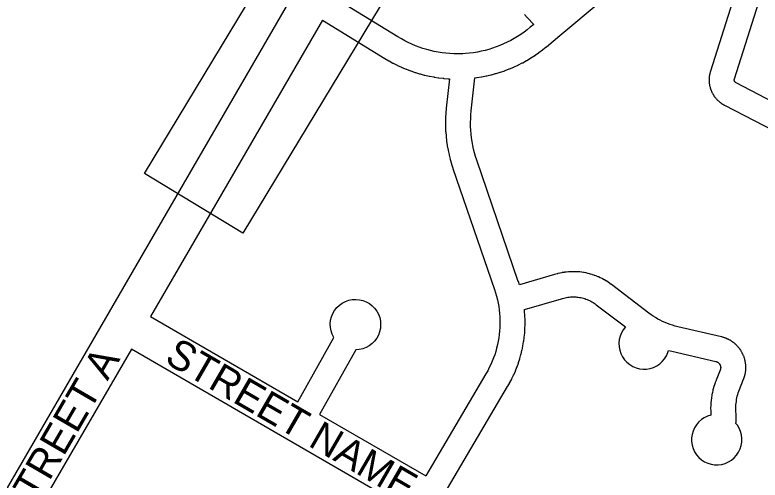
# Model space of a CAD drawing. Extents: x 599744 to 600217, y 4827560 to 4828065.
# Drawn here: x 600007.45 to 600025.18, y 4827978.51 to 4827989.56 of the extents above; entities that cross this region are included whole.
import ezdxf

# ---------------------------------------------------------------- set-up
doc = ezdxf.new("R2010")
doc.units = 0
doc.layers.add('G-ANNO-KEYP', color=7, linetype='Continuous')

msp = doc.modelspace()

# ---------------------------------------------------------------- linework, layer by layer
at = {"layer": 'G-ANNO-KEYP'}
msp.add_lwpolyline([(600010.535, 4827985.796), (600028.374, 4828015.258), (600030.714, 4828013.841), (600012.874, 4827984.379)], close=True, dxfattribs=at)
msp.add_lwpolyline([(600010.535, 4827985.796), (600028.374, 4828015.258), (600030.714, 4828013.841), (600012.874, 4827984.379)], close=True, dxfattribs=at)
for points in [[(600024.631, 4827990.207), (600023.999, 4827988.222), (600023.999, 4827988.219), (600023.997, 4827988.217), (600023.993, 4827988.204), (600023.993, 4827988.199), (600023.991, 4827988.194), (600023.987, 4827988.181), (600023.987, 4827988.175), (600023.985, 4827988.17), (600023.982, 4827988.157), (600023.981, 4827988.151), (600023.98, 4827988.146), (600023.977, 4827988.133), (600023.977, 4827988.126), (600023.975, 4827988.123), (600023.973, 4827988.109)], [(600024.569, 4827987.995), (600024.569, 4827987.998), (600024.568, 4827988), (600024.567, 4827988.003), (600024.567, 4827988.006), (600024.567, 4827988.009), (600024.566, 4827988.011), (600024.566, 4827988.014), (600024.566, 4827988.016), (600024.566, 4827988.019), (600024.566, 4827988.022), (600024.566, 4827988.025), (600024.567, 4827988.027), (600024.567, 4827988.03), (600024.568, 4827988.033), (600024.568, 4827988.035), (600024.569, 4827988.038), (600024.57, 4827988.043), (600025.2, 4827990.023)], [(600005.355, 4827974.888), (600005.664, 4827975.381), (600005.716, 4827975.467), (600005.764, 4827975.555), (600006.681, 4827977.304), (600006.685, 4827977.31), (600006.685, 4827977.312), (600006.748, 4827977.426), (600006.753, 4827977.433), (600006.753, 4827977.435), (600014.004, 4827989.912)], [(600019.578, 4827989.574), (600019.642, 4827989.504), (600019.795, 4827989.334), (600019.715, 4827989.268), (600019.64, 4827989.207), (600019.565, 4827989.151), (600019.489, 4827989.097), (600019.41, 4827989.046), (600019.33, 4827988.998), (600019.248, 4827988.953), (600019.165, 4827988.911), (600019.08, 4827988.871), (600018.993, 4827988.834), (600018.906, 4827988.801), (600018.818, 4827988.77), (600018.728, 4827988.743), (600018.638, 4827988.719), (600018.547, 4827988.697), (600018.455, 4827988.679), (600018.362, 4827988.665), (600018.27, 4827988.653), (600018.176, 4827988.645), (600018.108, 4827988.641), (600018.108, 4827988.641), (600018.083, 4827988.639), (600017.989, 4827988.638), (600017.896, 4827988.639), (600017.802, 4827988.643), (600017.709, 4827988.651), (600017.616, 4827988.662), (600017.524, 4827988.677), (600017.431, 4827988.694), (600017.34, 4827988.715), (600017.25, 4827988.739), (600017.16, 4827988.765), (600017.071, 4827988.796), (600016.984, 4827988.828), (600016.898, 4827988.865), (600016.813, 4827988.904), (600016.728, 4827988.946), (600016.647, 4827988.99), (600016.564, 4827989.039), (600015.071, 4827989.958)], [(600020.096, 4827988.806), (600020.097, 4827988.806), (600020.417, 4827989.073), (600021.425, 4827989.916)], [(600014.77, 4827989.44), (600010.677, 4827982.397)], [(600014.77, 4827989.44), (600016.252, 4827988.528), (600016.253, 4827988.528), (600016.257, 4827988.525), (600016.346, 4827988.472), (600016.348, 4827988.472), (600016.355, 4827988.467), (600016.446, 4827988.418), (600016.449, 4827988.417), (600016.456, 4827988.413), (600016.549, 4827988.366), (600016.551, 4827988.366), (600016.558, 4827988.362), (600016.652, 4827988.318), (600016.656, 4827988.318), (600016.662, 4827988.314), (600016.758, 4827988.274), (600016.762, 4827988.273), (600016.767, 4827988.27), (600016.865, 4827988.233), (600016.869, 4827988.233), (600016.875, 4827988.23), (600016.973, 4827988.197), (600016.978, 4827988.196), (600016.983, 4827988.193), (600017.082, 4827988.164), (600017.088, 4827988.163), (600017.092, 4827988.161), (600017.193, 4827988.134), (600017.199, 4827988.134), (600017.203, 4827988.132), (600017.305, 4827988.109), (600017.311, 4827988.109), (600017.315, 4827988.107), (600017.417, 4827988.087), (600017.424, 4827988.087), (600017.427, 4827988.086), (600017.53, 4827988.07), (600017.537, 4827988.07), (600017.54, 4827988.068), (600017.643, 4827988.056), (600017.651, 4827988.056), (600017.654, 4827988.055), (600017.757, 4827988.046), (600017.791, 4827988.047), (600017.715, 4827987.343), (600017.715, 4827987.339), (600017.714, 4827987.338), (600017.705, 4827987.237), (600017.705, 4827987.229)], [(600018.31, 4827987.281), (600018.396, 4827988.065), (600018.442, 4827988.071), (600018.442, 4827988.071), (600018.452, 4827988.073), (600018.555, 4827988.089), (600018.555, 4827988.089), (600018.565, 4827988.091), (600018.667, 4827988.111), (600018.668, 4827988.111), (600018.677, 4827988.113), (600018.778, 4827988.136), (600018.78, 4827988.137), (600018.788, 4827988.139), (600018.889, 4827988.166), (600018.891, 4827988.167), (600018.899, 4827988.169), (600018.998, 4827988.199), (600019, 4827988.201), (600019.008, 4827988.203), (600019.106, 4827988.237), (600019.109, 4827988.238), (600019.116, 4827988.24), (600019.213, 4827988.277), (600019.216, 4827988.279), (600019.223, 4827988.281), (600019.319, 4827988.322), (600019.322, 4827988.324), (600019.328, 4827988.326), (600019.422, 4827988.37), (600019.426, 4827988.373), (600019.432, 4827988.375), (600019.524, 4827988.422), (600019.528, 4827988.425), (600019.533, 4827988.427), (600019.624, 4827988.477), (600019.628, 4827988.48), (600019.633, 4827988.482), (600019.723, 4827988.536), (600019.727, 4827988.54), (600019.731, 4827988.541), (600019.819, 4827988.598), (600019.823, 4827988.602), (600019.827, 4827988.603), (600019.913, 4827988.663), (600019.917, 4827988.668), (600019.921, 4827988.669), (600020.004, 4827988.731), (600020.009, 4827988.737), (600020.012, 4827988.738), (600020.093, 4827988.803), (600020.096, 4827988.806)], [(600023.973, 4827988.109), (600023.973, 4827988.102), (600023.972, 4827988.098), (600023.971, 4827988.085), (600023.971, 4827988.077), (600023.97, 4827988.075), (600023.969, 4827988.061), (600023.969, 4827988.053), (600023.968, 4827988.05), (600023.967, 4827988.037), (600023.968, 4827988.028), (600023.967, 4827988.026), (600023.967, 4827988.013), (600023.968, 4827988.003), (600023.967, 4827988.002), (600023.968, 4827987.989), (600023.969, 4827987.979), (600023.968, 4827987.978), (600023.969, 4827987.965), (600023.97, 4827987.954), (600023.97, 4827987.954), (600023.972, 4827987.94), (600023.972, 4827987.935), (600023.973, 4827987.93), (600023.975, 4827987.916), (600023.975, 4827987.916), (600023.976, 4827987.906), (600023.979, 4827987.893), (600023.979, 4827987.892), (600023.981, 4827987.882), (600023.984, 4827987.869), (600023.984, 4827987.868), (600023.986, 4827987.858), (600023.99, 4827987.845), (600023.991, 4827987.844), (600023.992, 4827987.835), (600023.996, 4827987.822), (600023.997, 4827987.82), (600023.999, 4827987.812), (600024.004, 4827987.799), (600024.005, 4827987.797), (600024.007, 4827987.789), (600024.012, 4827987.776), (600024.014, 4827987.773), (600024.016, 4827987.766), (600024.021, 4827987.754), (600024.023, 4827987.75), (600024.025, 4827987.744), (600024.031, 4827987.732), (600024.034, 4827987.728), (600024.035, 4827987.722), (600024.041, 4827987.71)], [(600026.024, 4827987.215), (600024.609, 4827987.949), (600024.604, 4827987.952), (600024.602, 4827987.953), (600024.6, 4827987.955), (600024.597, 4827987.956), (600024.595, 4827987.958), (600024.593, 4827987.96), (600024.591, 4827987.961), (600024.589, 4827987.963), (600024.587, 4827987.965), (600024.585, 4827987.967), (600024.584, 4827987.969), (600024.582, 4827987.971), (600024.58, 4827987.973), (600024.579, 4827987.976), (600024.577, 4827987.978), (600024.576, 4827987.98), (600024.575, 4827987.983), (600024.573, 4827987.985), (600024.572, 4827987.987), (600024.571, 4827987.99), (600024.57, 4827987.993), (600024.569, 4827987.995)], [(600024.041, 4827987.71), (600024.045, 4827987.706), (600024.046, 4827987.7), (600024.053, 4827987.689), (600024.056, 4827987.684), (600024.058, 4827987.679), (600024.065, 4827987.668), (600024.069, 4827987.663), (600024.071, 4827987.658), (600024.078, 4827987.647), (600024.082, 4827987.642), (600024.084, 4827987.638), (600024.092, 4827987.627), (600024.096, 4827987.622), (600024.098, 4827987.618), (600024.106, 4827987.608), (600024.111, 4827987.602), (600024.113, 4827987.599), (600024.121, 4827987.589), (600024.127, 4827987.583), (600024.128, 4827987.58), (600024.137, 4827987.57), (600024.143, 4827987.565), (600024.144, 4827987.562), (600024.153, 4827987.553), (600024.16, 4827987.546), (600024.161, 4827987.545), (600024.17, 4827987.535), (600024.177, 4827987.529), (600024.178, 4827987.528), (600024.188, 4827987.519), (600024.196, 4827987.512), (600024.196, 4827987.511), (600024.206, 4827987.503), (600024.214, 4827987.496), (600024.214, 4827987.496), (600024.225, 4827987.487), (600024.228, 4827987.485), (600024.233, 4827987.481), (600024.244, 4827987.473), (600024.244, 4827987.473), (600024.253, 4827987.466), (600024.264, 4827987.459), (600024.265, 4827987.459), (600024.273, 4827987.453), (600024.284, 4827987.446), (600024.285, 4827987.445), (600024.294, 4827987.44), (600024.305, 4827987.433), (600024.307, 4827987.433)], [(600024.307, 4827987.433), (600024.314, 4827987.428), (600024.326, 4827987.422), (600024.327, 4827987.421), (600024.331, 4827987.419), (600025.746, 4827986.685)], [(600017.705, 4827987.229), (600017.704, 4827987.227), (600017.698, 4827987.126), (600017.699, 4827987.118), (600017.698, 4827987.116), (600017.696, 4827987.015), (600017.696, 4827987.006), (600017.696, 4827987.005), (600017.697, 4827986.903), (600017.697, 4827986.894), (600017.697, 4827986.893), (600017.701, 4827986.792), (600017.702, 4827986.783), (600017.702, 4827986.782), (600017.71, 4827986.681), (600017.711, 4827986.671), (600017.711, 4827986.671), (600017.722, 4827986.571), (600017.722, 4827986.567), (600017.723, 4827986.561), (600017.738, 4827986.46), (600017.738, 4827986.46), (600017.739, 4827986.451), (600017.757, 4827986.351), (600017.758, 4827986.35), (600017.759, 4827986.341), (600017.781, 4827986.242), (600017.781, 4827986.241), (600017.783, 4827986.232), (600017.808, 4827986.134), (600017.809, 4827986.133), (600017.81, 4827986.124), (600017.838, 4827986.027), (600017.839, 4827986.025), (600017.841, 4827986.017), (600017.872, 4827985.921), (600017.873, 4827985.92), (600017.874, 4827985.916), (600018.862, 4827983.036), (600018.888, 4827982.955), (600018.911, 4827982.875), (600018.931, 4827982.795), (600018.948, 4827982.714), (600018.963, 4827982.632), (600018.974, 4827982.55), (600018.983, 4827982.467), (600018.989, 4827982.385), (600018.992, 4827982.302), (600018.992, 4827982.219), (600018.99, 4827982.136), (600018.984, 4827982.054), (600018.976, 4827981.971)], [(600020.672, 4827983.459), (600020.672, 4827983.459), (600020.63, 4827983.457), (600020.62, 4827983.456), (600020.62, 4827983.456), (600020.578, 4827983.452), (600020.569, 4827983.451), (600020.568, 4827983.451), (600020.528, 4827983.446), (600020.528, 4827983.446), (600020.527, 4827983.446), (600020.527, 4827983.446), (600020.527, 4827983.446), (600020.517, 4827983.444), (600020.476, 4827983.437), (600020.475, 4827983.437), (600020.466, 4827983.436), (600020.425, 4827983.427), (600020.424, 4827983.427), (600020.415, 4827983.425), (600020.374, 4827983.416), (600020.373, 4827983.415), (600020.365, 4827983.413), (600020.354, 4827983.41), (600020.354, 4827983.41), (600020.354, 4827983.41), (600020.324, 4827983.402), (600020.324, 4827983.402), (600020.32, 4827983.401), (600020.29, 4827983.393), (600020.29, 4827983.393), (600020.29, 4827983.392), (600019.455, 4827983.15), (600019.431, 4827983.223), (600019.43, 4827983.224), (600019.429, 4827983.228), (600018.441, 4827986.108), (600018.412, 4827986.197), (600018.387, 4827986.285), (600018.365, 4827986.373), (600018.346, 4827986.462), (600018.33, 4827986.552), (600018.316, 4827986.642), (600018.306, 4827986.732), (600018.299, 4827986.824), (600018.295, 4827986.914), (600018.294, 4827987.006), (600018.297, 4827987.097), (600018.302, 4827987.188), (600018.31, 4827987.281)], [(600021.521, 4827983.239), (600021.513, 4827983.244), (600021.478, 4827983.265), (600021.476, 4827983.265), (600021.469, 4827983.27), (600021.432, 4827983.29), (600021.43, 4827983.29), (600021.423, 4827983.295), (600021.386, 4827983.313), (600021.383, 4827983.314), (600021.376, 4827983.317), (600021.339, 4827983.335), (600021.335, 4827983.335), (600021.329, 4827983.339), (600021.291, 4827983.355), (600021.287, 4827983.355), (600021.281, 4827983.358), (600021.242, 4827983.373), (600021.238, 4827983.373), (600021.232, 4827983.376), (600021.193, 4827983.389), (600021.188, 4827983.39), (600021.183, 4827983.393), (600021.143, 4827983.404), (600021.138, 4827983.405), (600021.133, 4827983.407), (600021.093, 4827983.418), (600021.088, 4827983.418), (600021.083, 4827983.42), (600021.043, 4827983.429), (600021.036, 4827983.429), (600021.033, 4827983.431), (600020.992, 4827983.439), (600020.985, 4827983.439), (600020.981, 4827983.44), (600020.94, 4827983.447), (600020.933, 4827983.447), (600020.93, 4827983.448), (600020.889, 4827983.453), (600020.881, 4827983.453), (600020.879, 4827983.454), (600020.837, 4827983.457), (600020.829, 4827983.457), (600020.827, 4827983.458), (600020.785, 4827983.46), (600020.777, 4827983.459), (600020.775, 4827983.46), (600020.734, 4827983.46), (600020.725, 4827983.46), (600020.723, 4827983.46), (600020.682, 4827983.459), (600020.672, 4827983.459)], [(600024.465, 4827981.83), (600024.457, 4827981.835), (600024.443, 4827981.843), (600024.441, 4827981.843), (600024.434, 4827981.848), (600024.419, 4827981.855), (600024.416, 4827981.856), (600024.409, 4827981.86), (600024.395, 4827981.866), (600024.391, 4827981.867), (600024.385, 4827981.871), (600024.37, 4827981.877), (600024.366, 4827981.877), (600024.36, 4827981.881), (600024.345, 4827981.886), (600024.34, 4827981.887), (600024.335, 4827981.89), (600024.319, 4827981.895), (600024.314, 4827981.895), (600024.309, 4827981.898), (600024.293, 4827981.903), (600024.288, 4827981.903), (600024.283, 4827981.905), (600024.267, 4827981.909), (600024.264, 4827981.909), (600024.262, 4827981.911), (600023.223, 4827982.152), (600023.159, 4827982.169), (600023.098, 4827982.186), (600023.038, 4827982.206), (600022.979, 4827982.228), (600022.92, 4827982.252), (600022.862, 4827982.278), (600022.805, 4827982.306), (600022.75, 4827982.335), (600022.695, 4827982.368), (600022.641, 4827982.401), (600022.589, 4827982.437), (600022.536, 4827982.476), (600021.646, 4827983.154), (600021.646, 4827983.154), (600021.642, 4827983.157), (600021.609, 4827983.181), (600021.608, 4827983.181), (600021.6, 4827983.187), (600021.566, 4827983.211), (600021.565, 4827983.211), (600021.557, 4827983.216), (600021.522, 4827983.239), (600021.521, 4827983.239)], [(600014.185, 4827980.367), (600015.04, 4827981.894), (600015.038, 4827981.897), (600015.001, 4827981.973), (600014.974, 4827982.053), (600014.959, 4827982.137), (600014.955, 4827982.221), (600014.964, 4827982.306), (600014.985, 4827982.388), (600015.017, 4827982.467), (600015.059, 4827982.54), (600015.112, 4827982.606), (600015.173, 4827982.665), (600015.242, 4827982.714), (600015.318, 4827982.753), (600015.398, 4827982.781), (600015.481, 4827982.797), (600015.566, 4827982.802), (600015.65, 4827982.794), (600015.733, 4827982.775), (600015.812, 4827982.744), (600015.886, 4827982.703), (600015.953, 4827982.651), (600016.012, 4827982.591), (600016.062, 4827982.522), (600016.103, 4827982.448), (600016.132, 4827982.368), (600016.149, 4827982.285), (600016.155, 4827982.2), (600016.149, 4827982.116), (600016.131, 4827982.033), (600016.101, 4827981.954), (600016.061, 4827981.879), (600016.01, 4827981.811), (600015.951, 4827981.751), (600015.883, 4827981.7), (600015.809, 4827981.658), (600015.73, 4827981.628), (600015.647, 4827981.609), (600015.562, 4827981.602), (600014.703, 4827980.067)], [(600019.591, 4827982.309), (600019.59, 4827982.318), (600019.591, 4827982.319), (600019.587, 4827982.412), (600019.587, 4827982.422), (600019.587, 4827982.422), (600019.58, 4827982.515), (600019.579, 4827982.525), (600019.579, 4827982.526), (600019.575, 4827982.561), (600020.457, 4827982.817), (600020.457, 4827982.817), (600020.484, 4827982.825), (600020.511, 4827982.832), (600020.511, 4827982.832), (600020.516, 4827982.834), (600020.547, 4827982.841), (600020.577, 4827982.847), (600020.608, 4827982.852), (600020.639, 4827982.856), (600020.67, 4827982.859), (600020.701, 4827982.861), (600020.732, 4827982.862), (600020.763, 4827982.861), (600020.794, 4827982.86), (600020.825, 4827982.857), (600020.856, 4827982.854), (600020.887, 4827982.849), (600020.918, 4827982.843), (600020.948, 4827982.837), (600020.978, 4827982.829), (600021.008, 4827982.82), (600021.038, 4827982.81), (600021.067, 4827982.799), (600021.096, 4827982.787), (600021.124, 4827982.774), (600021.152, 4827982.761), (600021.179, 4827982.746), (600021.206, 4827982.73), (600021.233, 4827982.713), (600021.258, 4827982.696), (600021.285, 4827982.676), (600021.979, 4827982.147), (600021.926, 4827982.081), (600021.884, 4827982.007), (600021.852, 4827981.929), (600021.832, 4827981.846), (600021.823, 4827981.762), (600021.827, 4827981.677), (600021.842, 4827981.594), (600021.869, 4827981.514), (600021.907, 4827981.438)], [(600010.677, 4827982.397), (600014.185, 4827980.367)], [(600017.746, 4827978.306), (600019.176, 4827980.731), (600019.176, 4827980.732), (600019.178, 4827980.736), (600019.224, 4827980.817), (600019.225, 4827980.819), (600019.229, 4827980.826), (600019.272, 4827980.909), (600019.273, 4827980.911), (600019.277, 4827980.918), (600019.317, 4827981.002), (600019.318, 4827981.005), (600019.322, 4827981.011), (600019.359, 4827981.097), (600019.359, 4827981.1), (600019.363, 4827981.106), (600019.397, 4827981.193), (600019.398, 4827981.197), (600019.401, 4827981.203), (600019.432, 4827981.29), (600019.433, 4827981.295), (600019.436, 4827981.3), (600019.464, 4827981.389), (600019.464, 4827981.394), (600019.467, 4827981.399), (600019.492, 4827981.489), (600019.492, 4827981.494), (600019.495, 4827981.499), (600019.517, 4827981.589), (600019.517, 4827981.595), (600019.519, 4827981.599), (600019.538, 4827981.691), (600019.538, 4827981.697), (600019.54, 4827981.701), (600019.556, 4827981.793), (600019.556, 4827981.799), (600019.557, 4827981.803), (600019.57, 4827981.895), (600019.57, 4827981.903), (600019.571, 4827981.905), (600019.581, 4827981.998), (600019.58, 4827982.006), (600019.581, 4827982.009), (600019.588, 4827982.102), (600019.587, 4827982.11), (600019.588, 4827982.112), (600019.591, 4827982.205), (600019.591, 4827982.214), (600019.591, 4827982.215), (600019.591, 4827982.309)], [(600018.976, 4827981.971), (600018.965, 4827981.889), (600018.951, 4827981.807), (600018.934, 4827981.726), (600018.914, 4827981.646), (600018.892, 4827981.566), (600018.867, 4827981.487), (600018.839, 4827981.409), (600018.808, 4827981.332), (600018.775, 4827981.256), (600018.739, 4827981.181), (600018.701, 4827981.107), (600018.659, 4827981.033), (600017.228, 4827978.606)], [(600024.768, 4827981.502), (600024.766, 4827981.508), (600024.759, 4827981.522), (600024.756, 4827981.526), (600024.754, 4827981.532), (600024.747, 4827981.546), (600024.743, 4827981.55), (600024.741, 4827981.555), (600024.733, 4827981.569), (600024.729, 4827981.574), (600024.727, 4827981.579), (600024.719, 4827981.592), (600024.714, 4827981.597), (600024.713, 4827981.601), (600024.704, 4827981.614), (600024.699, 4827981.619), (600024.697, 4827981.623), (600024.687, 4827981.636), (600024.682, 4827981.641), (600024.681, 4827981.644), (600024.671, 4827981.657), (600024.665, 4827981.663), (600024.664, 4827981.665), (600024.653, 4827981.678), (600024.647, 4827981.683), (600024.646, 4827981.685), (600024.635, 4827981.697), (600024.629, 4827981.703), (600024.628, 4827981.705), (600024.616, 4827981.716), (600024.609, 4827981.723), (600024.608, 4827981.724), (600024.597, 4827981.735), (600024.589, 4827981.741), (600024.589, 4827981.742), (600024.577, 4827981.753), (600024.568, 4827981.759), (600024.568, 4827981.76), (600024.556, 4827981.77), (600024.552, 4827981.773), (600024.547, 4827981.776), (600024.534, 4827981.786), (600024.534, 4827981.786), (600024.525, 4827981.792), (600024.512, 4827981.801), (600024.511, 4827981.802), (600024.503, 4827981.807), (600024.49, 4827981.816), (600024.488, 4827981.816), (600024.481, 4827981.822), (600024.467, 4827981.83), (600024.465, 4827981.83)], [(600010.225, 4827981.619), (600007.533, 4827976.987), (600007.475, 4827976.881), (600006.558, 4827975.134), (600006.555, 4827975.128), (600006.554, 4827975.126), (600006.5, 4827975.027), (600006.492, 4827975.015), (600006.491, 4827975.012), (600006.433, 4827974.915), (600006.429, 4827974.909), (600006.429, 4827974.908), (600006.144, 4827974.453)], [(600016.771, 4827977.831), (600010.225, 4827981.619)], [(600021.907, 4827981.438), (600021.955, 4827981.368), (600022.013, 4827981.306), (600022.079, 4827981.252), (600022.151, 4827981.209), (600022.229, 4827981.176), (600022.311, 4827981.154), (600022.396, 4827981.144), (600022.48, 4827981.147), (600022.564, 4827981.161), (600022.645, 4827981.186), (600022.721, 4827981.223), (600022.792, 4827981.271), (600022.855, 4827981.327), (600022.909, 4827981.392), (600022.954, 4827981.464), (600022.988, 4827981.542), (600023.003, 4827981.591), (600023.08, 4827981.571), (600023.083, 4827981.571), (600023.085, 4827981.57), (600024.124, 4827981.328), (600024.132, 4827981.326), (600024.137, 4827981.324), (600024.142, 4827981.323), (600024.147, 4827981.321), (600024.152, 4827981.319), (600024.157, 4827981.317), (600024.162, 4827981.314), (600024.167, 4827981.312), (600024.171, 4827981.309), (600024.176, 4827981.306), (600024.18, 4827981.303), (600024.184, 4827981.3), (600024.189, 4827981.296), (600024.193, 4827981.293), (600024.197, 4827981.289), (600024.201, 4827981.285), (600024.204, 4827981.281), (600024.208, 4827981.277), (600024.211, 4827981.273), (600024.214, 4827981.269), (600024.218, 4827981.264), (600024.22, 4827981.26), (600024.223, 4827981.255), (600024.226, 4827981.25), (600024.228, 4827981.245), (600024.23, 4827981.241), (600024.233, 4827981.235), (600024.234, 4827981.231)], [(600024.835, 4827981.079), (600024.835, 4827981.086), (600024.836, 4827981.089), (600024.838, 4827981.106), (600024.838, 4827981.113), (600024.839, 4827981.116), (600024.84, 4827981.132), (600024.84, 4827981.141), (600024.841, 4827981.143), (600024.841, 4827981.159), (600024.841, 4827981.168), (600024.842, 4827981.17), (600024.842, 4827981.186), (600024.841, 4827981.195), (600024.842, 4827981.197), (600024.841, 4827981.213), (600024.84, 4827981.223), (600024.84, 4827981.223), (600024.839, 4827981.239), (600024.838, 4827981.25), (600024.838, 4827981.251), (600024.837, 4827981.267), (600024.836, 4827981.272), (600024.835, 4827981.277), (600024.833, 4827981.293), (600024.833, 4827981.293), (600024.832, 4827981.304), (600024.829, 4827981.319), (600024.828, 4827981.32), (600024.827, 4827981.33), (600024.823, 4827981.346), (600024.823, 4827981.347), (600024.821, 4827981.356), (600024.817, 4827981.372), (600024.816, 4827981.374), (600024.814, 4827981.382), (600024.809, 4827981.398), (600024.808, 4827981.4), (600024.806, 4827981.408), (600024.801, 4827981.423), (600024.8, 4827981.426), (600024.798, 4827981.434), (600024.792, 4827981.449), (600024.79, 4827981.451), (600024.788, 4827981.459), (600024.782, 4827981.474), (600024.78, 4827981.477), (600024.778, 4827981.484), (600024.771, 4827981.498), (600024.768, 4827981.502)], [(600024.234, 4827981.231), (600024.236, 4827981.225), (600024.238, 4827981.22), (600024.239, 4827981.215), (600024.24, 4827981.21), (600024.241, 4827981.204), (600024.242, 4827981.199), (600024.242, 4827981.194), (600024.243, 4827981.188), (600024.243, 4827981.183), (600024.243, 4827981.177), (600024.243, 4827981.172), (600024.242, 4827981.166), (600024.242, 4827981.161), (600024.241, 4827981.156), (600024.24, 4827981.15), (600024.239, 4827981.146), (600024.237, 4827981.14), (600024.236, 4827981.135), (600024.234, 4827981.13), (600024.231, 4827981.122), (600024.134, 4827980.879), (600024.134, 4827980.878), (600024.132, 4827980.875), (600024.114, 4827980.827), (600024.113, 4827980.822), (600024.11, 4827980.817), (600024.094, 4827980.768), (600024.093, 4827980.764), (600024.091, 4827980.758), (600024.076, 4827980.709), (600024.075, 4827980.704), (600024.073, 4827980.699), (600024.06, 4827980.65), (600024.059, 4827980.644), (600024.057, 4827980.64), (600024.046, 4827980.59), (600024.045, 4827980.584), (600024.043, 4827980.579), (600024.034, 4827980.529), (600024.033, 4827980.522), (600024.032, 4827980.519), (600024.024, 4827980.468), (600024.024, 4827980.461), (600024.022, 4827980.458), (600024.016, 4827980.407), (600024.016, 4827980.399), (600024.015, 4827980.397), (600024.01, 4827980.345), (600024.01, 4827980.337), (600024.01, 4827980.335), (600024.007, 4827980.284)], [(600024.612, 4827979.905), (600024.614, 4827979.933), (600024.613, 4827979.942), (600024.614, 4827979.944), (600024.615, 4827979.971), (600024.615, 4827979.981), (600024.615, 4827979.982), (600024.615, 4827980.01), (600024.614, 4827980.019), (600024.615, 4827980.02), (600024.613, 4827980.048), (600024.612, 4827980.058), (600024.613, 4827980.059), (600024.61, 4827980.086), (600024.61, 4827980.086), (600024.61, 4827980.086), (600024.607, 4827980.133), (600024.605, 4827980.174), (600024.604, 4827980.215), (600024.605, 4827980.256), (600024.607, 4827980.297), (600024.611, 4827980.338), (600024.616, 4827980.379), (600024.622, 4827980.42), (600024.63, 4827980.46), (600024.639, 4827980.5), (600024.65, 4827980.54), (600024.662, 4827980.579), (600024.675, 4827980.619), (600024.691, 4827980.66), (600024.788, 4827980.902), (600024.788, 4827980.904), (600024.79, 4827980.907), (600024.796, 4827980.922), (600024.796, 4827980.927), (600024.799, 4827980.932), (600024.805, 4827980.948), (600024.805, 4827980.953), (600024.808, 4827980.958), (600024.812, 4827980.974), (600024.813, 4827980.979), (600024.815, 4827980.984), (600024.819, 4827980.999), (600024.82, 4827981.005), (600024.822, 4827981.01), (600024.825, 4827981.026), (600024.826, 4827981.032), (600024.828, 4827981.036), (600024.831, 4827981.052), (600024.831, 4827981.059), (600024.832, 4827981.063), (600024.835, 4827981.079)], [(600024.007, 4827980.284), (600024.007, 4827980.275), (600024.006, 4827980.273), (600024.005, 4827980.222), (600024.006, 4827980.213), (600024.005, 4827980.212), (600024.006, 4827980.16), (600024.007, 4827980.151), (600024.006, 4827980.15), (600024.011, 4827980.053), (600023.93, 4827980.028), (600023.853, 4827979.991), (600023.783, 4827979.944), (600023.719, 4827979.888), (600023.665, 4827979.823), (600023.619, 4827979.751), (600023.585, 4827979.674), (600023.561, 4827979.593), (600023.55, 4827979.509), (600023.55, 4827979.424), (600023.563, 4827979.34), (600023.587, 4827979.258), (600023.622, 4827979.181), (600023.668, 4827979.11), (600023.723, 4827979.046), (600023.787, 4827978.99), (600023.858, 4827978.944), (600023.935, 4827978.908), (600024.016, 4827978.884), (600024.1, 4827978.871), (600024.185, 4827978.87), (600024.269, 4827978.881), (600024.351, 4827978.904), (600024.428, 4827978.938), (600024.5, 4827978.983), (600024.565, 4827979.037), (600024.622, 4827979.1), (600024.669, 4827979.171), (600024.706, 4827979.247), (600024.732, 4827979.328), (600024.746, 4827979.411), (600024.748, 4827979.496), (600024.738, 4827979.58), (600024.717, 4827979.662), (600024.684, 4827979.74), (600024.64, 4827979.813), (600024.607, 4827979.856), (600024.611, 4827979.895), (600024.611, 4827979.903), (600024.612, 4827979.905)], [(600014.703, 4827980.067), (600017.228, 4827978.606)]]:
    msp.add_lwpolyline(points, dxfattribs=at)

# ---------------------------------------------------------------- texts
for s, rotation, p in [('STREET NAME', 329.9428, (600010.986, 4827981.314)), ('STREET A', 59.8386, (600007.671, 4827977.434))]:
    msp.add_text(s, height=0.7, rotation=rotation, dxfattribs=at).set_placement(p)

doc.saveas('drawing.dxf')
